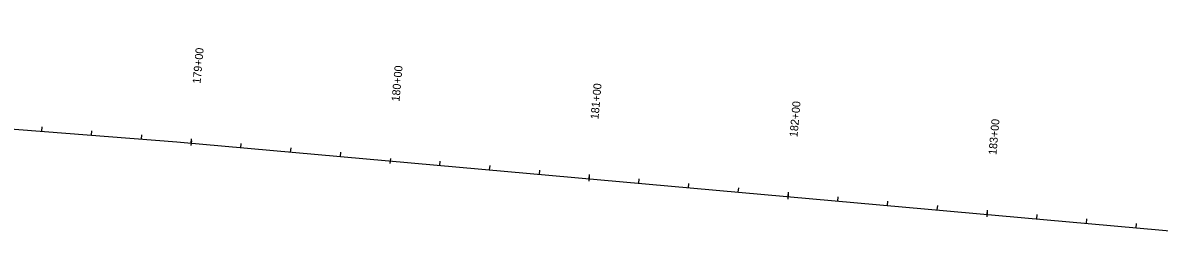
# Model space of a CAD drawing. Extents: x 20500393 to 20505339, y 7953466 to 7954298.
# Drawn here: x 20501525 to 20502094, y 7953855 to 7953969 of the extents above; entities that cross this region are included whole.
import ezdxf

# ---------------------------------------------------------------- set-up
doc = ezdxf.new("R2010")
doc.units = 0
for name, color, linetype in [('_CIVIL_CONSTRUCTION', 7, 'Continuous'), ('TextAlignmentLrg', 7, 'Continuous'), ('TextAlignmentSml', 7, 'Continuous')]:
    doc.layers.add(name, color=color, linetype=linetype)

msp = doc.modelspace()

# ---------------------------------------------------------------- linework, layer by layer
at = {"layer": '_CIVIL_CONSTRUCTION'}
for p, q in [((20500850.16, 7953968.94), (20501601.96, 7953909.2)), ((20500850.16, 7953968.94), (20501601.96, 7953909.2)), ((20501601.96, 7953909.2), (20502202.58, 7953855.42)), ((20501601.96, 7953909.2), (20502202.58, 7953855.42))]:
    msp.add_line(p, q, dxfattribs=at)
at = {"layer": 'TextAlignmentLrg'}
for p, q in [((20501609.18, 7953908.55), (20501609.37, 7953910.73)), ((20501708.89, 7953900.86), (20501708.67, 7953898.42)), ((20501808.38, 7953890.72), (20501808.58, 7953892.89)), ((20501907.98, 7953881.8), (20501908.18, 7953883.97)), ((20502007.59, 7953872.88), (20502007.78, 7953875.06))]:
    msp.add_line(p, q, dxfattribs=at)
at = {"layer": 'TextAlignmentSml'}
for p, q in [((20501534.42, 7953914.57), (20501534.59, 7953916.75)), ((20501559.34, 7953912.59), (20501559.52, 7953914.76)), ((20501584.26, 7953910.61), (20501584.44, 7953912.78)), ((20501609.29, 7953909.77), (20501609.07, 7953907.34)), ((20501634.08, 7953906.33), (20501634.28, 7953908.5)), ((20501658.98, 7953904.1), (20501659.18, 7953906.27)), ((20501683.88, 7953901.87), (20501684.08, 7953904.04)), ((20501708.89, 7953900.86), (20501708.67, 7953898.42)), ((20501733.68, 7953897.41), (20501733.88, 7953899.58)), ((20501758.58, 7953895.18), (20501758.78, 7953897.35)), ((20501783.48, 7953892.95), (20501783.68, 7953895.12)), ((20501808.49, 7953891.94), (20501808.27, 7953889.5)), ((20501833.28, 7953888.49), (20501833.48, 7953890.66)), ((20501858.18, 7953886.26), (20501858.38, 7953888.43)), ((20501883.08, 7953884.03), (20501883.28, 7953886.2)), ((20501908.09, 7953883.02), (20501907.88, 7953880.58)), ((20501932.88, 7953879.57), (20501933.08, 7953881.75)), ((20501957.79, 7953877.34), (20501957.98, 7953879.52)), ((20501982.69, 7953875.11), (20501982.88, 7953877.29)), ((20502007.7, 7953874.1), (20502007.48, 7953871.66)), ((20502032.49, 7953870.65), (20502032.68, 7953872.83)), ((20502057.39, 7953868.42), (20502057.58, 7953870.6)), ((20502082.29, 7953866.19), (20502082.48, 7953868.37))]:
    msp.add_line(p, q, dxfattribs=at)

# ---------------------------------------------------------------- texts
at = {"layer": 'TextAlignmentLrg'}
msp.add_text('180+00', height=4.008, rotation=84.8834, dxfattribs=at).set_placement((20501713.45, 7953929.34))
at = {"layer": 'TextAlignmentSml'}
for s, p in [('179+00', (20501613.85, 7953938.26)), ('180+00', (20501713.45, 7953929.34)), ('181+00', (20501813.05, 7953920.42)), ('182+00', (20501912.66, 7953911.5)), ('183+00', (20502012.26, 7953902.58))]:
    msp.add_text(s, height=4.008, rotation=84.8834, dxfattribs=at).set_placement(p)

doc.saveas('drawing.dxf')
